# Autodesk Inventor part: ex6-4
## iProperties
Author: Administrator
Created: 2001-09
Part Number: ex6-4
Document SubType Name: Modeling
Designer: Administrator
Control State: 0
Master: False
Checked Out: False
PropertySet Name: Design Tracking Control
Length Units: 11272
Angle Units: 11279
Time Units: 11290
Mass Units: 11286
Shininess: 3
Angle Display Precision: 2
Document Length Units: 11272
Document Angle Units: 11286
Document Time Units: 11279
Document Mass Units: 11290
Document Length Units Precision: 3
Document Angle Units Precision: 2
Compacted: False
PropertySet Name: _Private Model Information
Density: 0.0
Volumn: 0.0
Area: 0.0
PropertySet Name: Model Information
